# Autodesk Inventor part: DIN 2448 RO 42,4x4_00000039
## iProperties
Created: 2006-02
Part Number: DIN 2448 RO 42,4x4_00000039
Material: Default
Document SubType Name: Modeling
Designer: FranzK
Stock Number: DIN 2448 RO 42,4x4
Mass: 241.274 g
Surface Area: 1216.02 cm^2
Volume: 241.274 cm^3
Density: 1 g/cm^3
G_L: 500.000 mm
G_W: 42.400 mm
G_H: 42.400 mm
AFG_Item: 42.4 x 4
CSToolsMass: 0.2
CSToolsVolume: 241274.0
CSToolsArea: 1216.0
Author: FranzK
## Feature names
1. AFG_Detailed_DIN 2448 RO 42,4x4_00000039 [Extrusion]
2. AFG_Simplified_DIN 2448 RO 42,4x4_00000039 [Extrusion]
